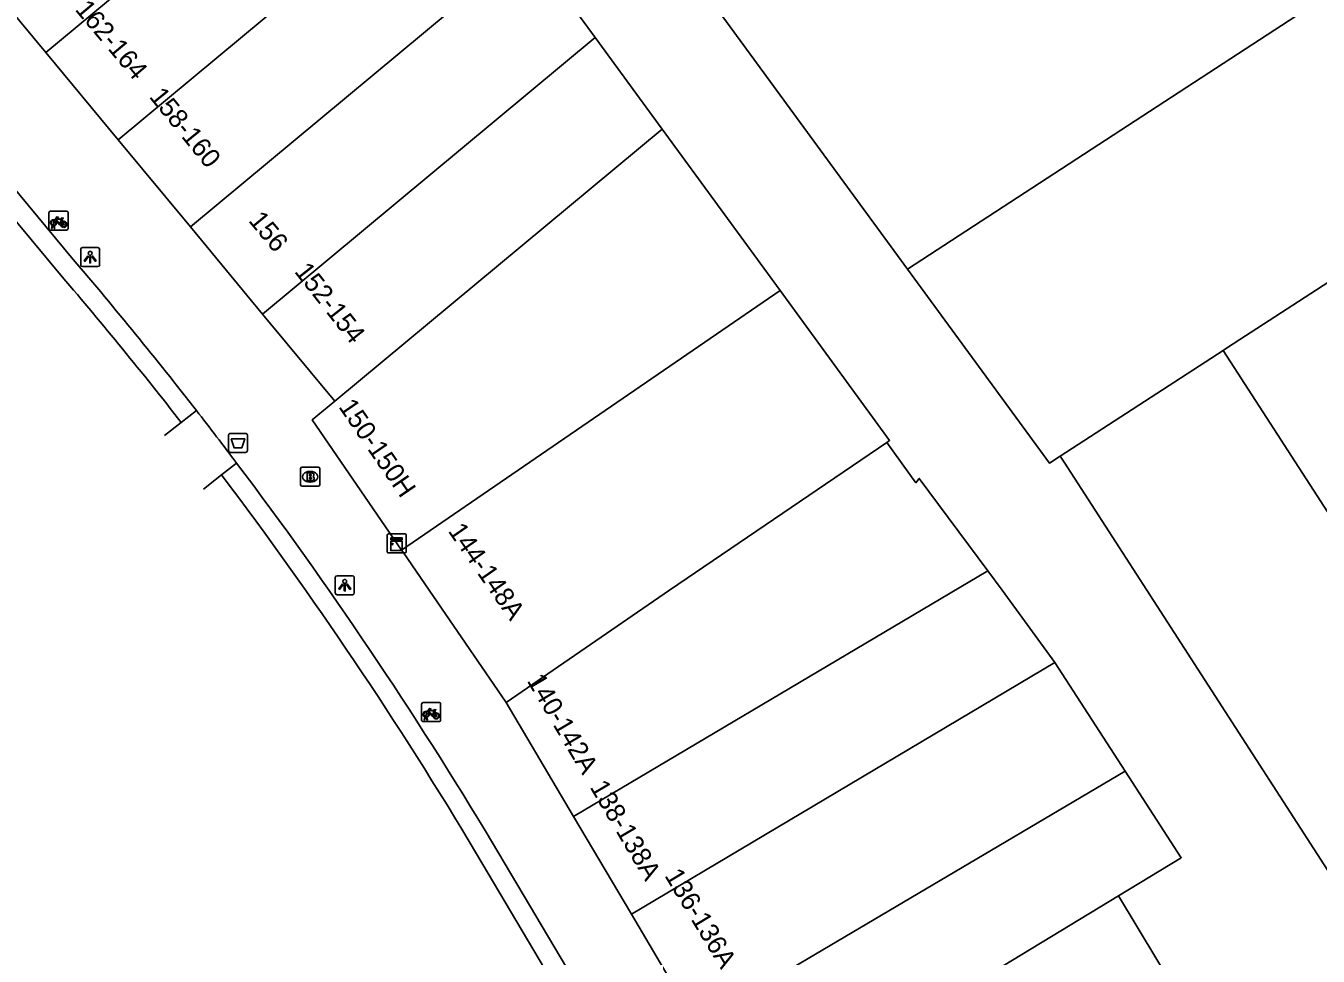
# Model space of a CAD drawing. Extents: x 160861 to 161308, y 384024 to 384878.
# Drawn here: x 161015.6 to 161083.4, y 384480.8 to 384529.6 of the extents above; entities that cross this region are included whole.
import ezdxf

# ---------------------------------------------------------------- set-up
doc = ezdxf.new("R2010")
doc.units = 0
for name, color, linetype in [('IMGEO_Afvalbak', 7, 'Continuous'), ('IMGEO_Brandkraan', 7, 'Continuous'), ('IMGEO_Fietsenrek', 7, 'Continuous'), ('IMGEO_Fietspad_gesloten', 7, 'Continuous'), ('IMGEO_Fietspad_open', 7, 'Continuous'), ('IMGEO_Kast', 7, 'Continuous'), ('IMGEO_Lichtpunt', 7, 'Continuous'), ('IMGEO_Pand', 7, 'Continuous'), ('IMGEO_Pand_nummerreeks', 7, 'Continuous')]:
    doc.layers.add(name, color=color, linetype=linetype)

msp = doc.modelspace()

# ---------------------------------------------------------------- linework, layer by layer
at = {"layer": 'IMGEO_Afvalbak'}
for p, q in [((161026.246, 384507.334), (161026.246, 384508.134)), ((161026.246, 384508.134), (161026.246, 384507.334)), ((161026.346, 384508.234), (161027.136, 384508.234)), ((161027.136, 384508.234), (161026.346, 384508.234)), ((161027.236, 384508.134), (161027.236, 384507.334)), ((161027.236, 384507.334), (161027.236, 384508.134)), ((161027.136, 384507.234), (161026.346, 384507.234)), ((161026.346, 384507.234), (161027.136, 384507.234))]:
    msp.add_line(p, q, dxfattribs=at)
msp.add_lwpolyline([(161026.389, 384507.948), (161027.093, 384507.948), (161026.944, 384507.478), (161026.538, 384507.478), (161026.389, 384507.948)], dxfattribs=at)
for centre, start, end in [((161026.346, 384508.134), 90, 180), ((161026.346, 384508.134), 90, 180), ((161027.136, 384508.134), 0, 90), ((161027.136, 384508.134), 360, 90), ((161026.346, 384507.334), 180, 270), ((161026.346, 384507.334), 180, 270), ((161027.136, 384507.334), 270, 0), ((161027.136, 384507.334), 270, 0)]:
    msp.add_arc(centre, 0.1, start, end, dxfattribs=at)
at = {"layer": 'IMGEO_Brandkraan'}
for p, q in [((161030.024, 384505.531), (161030.024, 384506.383)), ((161030.099, 384506.457), (161030.951, 384506.457)), ((161031.025, 384506.383), (161031.025, 384505.531)), ((161030.512, 384506.237), (161030.537, 384506.237)), ((161030.951, 384505.457), (161030.099, 384505.457)), ((161030.535, 384505.677), (161030.51, 384505.677))]:
    msp.add_line(p, q, dxfattribs=at)
for points in [[(161030.024, 384505.531), (161030.024, 384506.383)], [(161030.099, 384506.457), (161030.951, 384506.457)], [(161031.025, 384506.383), (161031.025, 384505.531)], [(161030.372, 384506.157), (161030.372, 384505.757), (161030.585, 384505.757)], [(161030.603, 384506.157), (161030.372, 384506.157)], [(161030.551, 384506.076), (161030.497, 384506.076), (161030.497, 384506)], [(161030.497, 384506), (161030.55, 384506)], [(161030.559, 384505.924), (161030.497, 384505.924), (161030.497, 384505.843)], [(161030.497, 384505.843), (161030.559, 384505.843)], [(161030.951, 384505.457), (161030.099, 384505.457)]]:
    msp.add_lwpolyline(points, dxfattribs=at)
for centre, radius, start, end in [((161030.101, 384506.381), 0.0765, 91.55205, 178.44795), ((161030.101, 384506.381), 0.0765, 91.55205, 178.44795), ((161030.949, 384506.381), 0.0765, 1.55205, 88.44795), ((161030.949, 384506.381), 0.0765, 1.55205, 88.44795), ((161030.552, 384506.038), 0.0379, 267.82845, 90.93552), ((161030.56, 384505.883), 0.0404, 269.87594, 90.50774), ((161030.591, 384506.008), 0.251, 268.66757, 293.53466), ((161030.607, 384506.012), 0.145, 59.4692, 91.53667), ((161030.632, 384506.059), 0.0922, 285.51372, 58.15012), ((161030.637, 384505.867), 0.105, 301.31148, 78.98903), ((161030.101, 384505.533), 0.0765, 181.55205, 268.44795), ((161030.101, 384505.533), 0.0765, 181.55205, 268.44795), ((161030.949, 384505.533), 0.0765, 271.55205, 358.44795), ((161030.949, 384505.533), 0.0765, 271.55205, 358.44795)]:
    msp.add_arc(centre, radius, start, end, dxfattribs=at)
for centre, major_axis, ratio, start_param, end_param in [((161030.511, 384505.957), (-0.387, 0.002), 0.722429, 4.712389, 7.853982), ((161030.536, 384505.957), (-0.39, 0.002), 0.717154, 1.570796, 4.712389)]:
    msp.add_ellipse(centre, major_axis=major_axis, ratio=ratio, start_param=start_param, end_param=end_param, dxfattribs=at)
at = {"layer": 'IMGEO_Fietsenrek'}
for p, q in [((161016.83, 384518.972), (161016.83, 384519.813)), ((161016.83, 384519.813), (161016.83, 384518.972)), ((161016.905, 384519.897), (161017.746, 384519.897)), ((161017.746, 384519.897), (161016.905, 384519.897)), ((161017.517, 384519.446), (161017.553, 384519.351)), ((161017.83, 384519.822), (161017.83, 384518.981)), ((161017.83, 384518.981), (161017.83, 384519.822)), ((161017.755, 384518.897), (161016.914, 384518.897)), ((161016.914, 384518.897), (161017.755, 384518.897)), ((161016.957, 384518.981), (161016.996, 384519.141)), ((161016.991, 384518.981), (161016.957, 384518.981)), ((161017.026, 384519.129), (161016.991, 384518.981)), ((161017.068, 384519.153), (161017.067, 384519.157)), ((161017.109, 384518.981), (161017.075, 384519.123)), ((161017.099, 384519.164), (161017.1, 384519.157)), ((161017.107, 384519.127), (161017.142, 384518.981)), ((161017.142, 384518.981), (161017.109, 384518.981)), ((161036.368, 384493.185), (161036.368, 384494.026)), ((161036.368, 384494.026), (161036.368, 384493.185)), ((161036.443, 384494.11), (161037.284, 384494.11)), ((161037.284, 384494.11), (161036.443, 384494.11)), ((161037.055, 384493.659), (161037.091, 384493.564)), ((161037.368, 384494.035), (161037.368, 384493.194)), ((161037.368, 384493.194), (161037.368, 384494.035)), ((161037.293, 384493.11), (161036.452, 384493.11)), ((161036.452, 384493.11), (161037.293, 384493.11)), ((161036.495, 384493.194), (161036.534, 384493.354)), ((161036.529, 384493.194), (161036.495, 384493.194)), ((161036.564, 384493.342), (161036.529, 384493.194)), ((161036.606, 384493.366), (161036.605, 384493.37)), ((161036.647, 384493.194), (161036.613, 384493.336)), ((161036.637, 384493.377), (161036.638, 384493.37)), ((161036.645, 384493.34), (161036.68, 384493.194)), ((161036.68, 384493.194), (161036.647, 384493.194))]:
    msp.add_line(p, q, dxfattribs=at)
for points in [[(161017.164, 384519.371), (161017.112, 384519.281), (161017.072, 384519.256), (161017.073, 384519.303), (161017.128, 384519.397)], [(161017.143, 384519.423), (161017.238, 384519.587), (161017.324, 384519.573), (161017.326, 384519.564), (161017.27, 384519.553), (161017.243, 384519.508), (161017.499, 384519.467)], [(161017.439, 384519.179), (161017.389, 384519.179), (161017.198, 384519.43), (161017.179, 384519.398)], [(161017.486, 384519.442), (161017.229, 384519.483), (161017.212, 384519.454), (161017.379, 384519.234), (161017.486, 384519.442)], [(161017.534, 384519.344), (161017.504, 384519.421), (161017.395, 384519.203), (161017.438, 384519.203)], [(161017.468, 384519.203), (161017.588, 384519.202), (161017.544, 384519.316)], [(161017.564, 384519.323), (161017.619, 384519.178), (161017.469, 384519.178)], [(161017.499, 384519.467), (161017.524, 384519.516), (161017.518, 384519.52), (161017.495, 384519.524), (161017.483, 384519.531), (161017.482, 384519.534), (161017.484, 384519.539), (161017.579, 384519.524), (161017.581, 384519.514), (161017.571, 384519.501), (161017.559, 384519.495), (161017.545, 384519.501), (161017.517, 384519.446)], [(161036.702, 384493.584), (161036.65, 384493.494), (161036.61, 384493.469), (161036.611, 384493.516), (161036.666, 384493.61)], [(161036.681, 384493.636), (161036.776, 384493.8), (161036.862, 384493.786), (161036.864, 384493.777), (161036.808, 384493.766), (161036.781, 384493.721), (161037.037, 384493.68)], [(161036.977, 384493.392), (161036.927, 384493.392), (161036.736, 384493.643), (161036.717, 384493.611)], [(161037.024, 384493.655), (161036.767, 384493.696), (161036.75, 384493.667), (161036.917, 384493.447), (161037.024, 384493.655)], [(161037.072, 384493.557), (161037.042, 384493.634), (161036.933, 384493.416), (161036.976, 384493.416)], [(161037.006, 384493.416), (161037.126, 384493.415), (161037.082, 384493.529)], [(161037.102, 384493.536), (161037.157, 384493.391), (161037.007, 384493.391)], [(161037.037, 384493.68), (161037.062, 384493.729), (161037.056, 384493.733), (161037.033, 384493.737), (161037.021, 384493.744), (161037.02, 384493.747), (161037.022, 384493.752), (161037.117, 384493.737), (161037.119, 384493.727), (161037.109, 384493.714), (161037.097, 384493.708), (161037.083, 384493.714), (161037.055, 384493.659)]]:
    msp.add_lwpolyline(points, dxfattribs=at)
for centre, radius, start, end in [((161016.908, 384519.819), 0.0779, 92.4484, 184.28452), ((161016.908, 384519.819), 0.0779, 92.4484, 184.28452), ((161017.07, 384519.282), 0.159, 62.67661, 242.13685), ((161017.07, 384519.282), 0.129, 63.31916, 238.90302), ((161017.07, 384519.282), 0.129, 283.60429, 43.43025), ((161017.07, 384519.282), 0.159, 283.5766, 46.60424), ((161017.597, 384519.198), 0.159, 113.3408, 178.32165), ((161017.597, 384519.198), 0.159, 187.0065, 105.77075), ((161017.597, 384519.198), 0.129, 113.92302, 177.95563), ((161017.597, 384519.198), 0.129, 188.67146, 104.58832), ((161017.752, 384519.819), 0.0779, 2.4484, 94.28452), ((161017.752, 384519.819), 0.0779, 2.4484, 94.28452), ((161016.908, 384518.975), 0.0779, 182.4484, 274.28452), ((161016.908, 384518.975), 0.0779, 182.4484, 274.28452), ((161017.05, 384519.153), 0.0499, 12.8025, 158.69338), ((161017.07, 384519.282), 0.159, 253.99666, 271.78671), ((161017.05, 384519.153), 0.0174, 12.8025, 163.45023), ((161017.07, 384519.282), 0.129, 253.41502, 269.02044), ((161017.752, 384518.975), 0.0779, 272.4484, 4.28452), ((161017.752, 384518.975), 0.0779, 272.4484, 4.28452), ((161036.446, 384494.032), 0.0779, 92.4484, 184.28452), ((161036.446, 384494.032), 0.0779, 92.4484, 184.28452), ((161036.608, 384493.495), 0.159, 62.67661, 242.13685), ((161036.608, 384493.495), 0.129, 63.31916, 238.90302), ((161036.608, 384493.495), 0.129, 283.60429, 43.43025), ((161036.608, 384493.495), 0.159, 283.5766, 46.60424), ((161037.135, 384493.411), 0.159, 113.3408, 178.32165), ((161037.135, 384493.411), 0.159, 187.0065, 105.77075), ((161037.135, 384493.411), 0.129, 113.92302, 177.95563), ((161037.135, 384493.411), 0.129, 188.67146, 104.58832), ((161037.29, 384494.032), 0.0779, 2.4484, 94.28452), ((161037.29, 384494.032), 0.0779, 2.4484, 94.28452), ((161036.446, 384493.188), 0.0779, 182.4484, 274.28452), ((161036.446, 384493.188), 0.0779, 182.4484, 274.28452), ((161036.588, 384493.366), 0.0499, 12.8025, 158.69338), ((161036.608, 384493.495), 0.159, 253.99666, 271.78671), ((161036.588, 384493.366), 0.0174, 12.8025, 163.45023), ((161036.608, 384493.495), 0.129, 253.41502, 269.02044), ((161037.29, 384493.188), 0.0779, 272.4484, 4.28452), ((161037.29, 384493.188), 0.0779, 272.4484, 4.28452)]:
    msp.add_arc(centre, radius, start, end, dxfattribs=at)
at = {"layer": 'IMGEO_Fietspad_gesloten'}
for points in [[(161017.521, 384516.451), (160978.487, 384563.462)], [(161022.895, 384508.122), (161023.763, 384508.809)], [(161024.93, 384505.299), (161025.88, 384506.051)], [(161062.919, 384446.259), (161039.255, 384486.177)]]:
    msp.add_lwpolyline(points, dxfattribs=at)
for centre, radius, start, end in [((160850.658, 384373.787), 219.536, 37.9543, 40.52973), ((160849.822, 384373.128), 220.601, 30.82769, 37.05261)]:
    msp.add_arc(centre, radius, start, end, dxfattribs=at)
at = {"layer": 'IMGEO_Fietspad_open'}
for points in [[(161018.1, 384517.358), (160990.437, 384550.764), (160979.348, 384564.156)], [(161024.556, 384509.436), (161023.763, 384508.809)], [(161025.88, 384506.051), (161026.669, 384506.676)], [(161063.799, 384446.778), (161040.086, 384486.747)]]:
    msp.add_lwpolyline(points, dxfattribs=at)
for centre, radius, start, end in [((160847.353, 384371.617), 224.489, 37.8739, 40.48243), ((160849.227, 384373.018), 222.149, 36.98868, 37.88519), ((160846.585, 384370.955), 225.5, 30.89645, 37.00358)]:
    msp.add_arc(centre, radius, start, end, dxfattribs=at)
at = {"layer": 'IMGEO_Kast'}
for p, q in [((161034.56, 384502.034), (161034.56, 384502.875)), ((161034.56, 384502.875), (161034.56, 384502.034)), ((161034.635, 384502.959), (161035.476, 384502.959)), ((161035.476, 384502.959), (161034.635, 384502.959)), ((161035.56, 384502.884), (161035.56, 384502.043)), ((161035.56, 384502.043), (161035.56, 384502.884)), ((161035.485, 384501.959), (161034.644, 384501.959)), ((161034.644, 384501.959), (161035.485, 384501.959))]:
    msp.add_line(p, q, dxfattribs=at)
for points in [[(161034.755, 384502.749), (161035.355, 384502.749), (161035.355, 384502.664), (161034.755, 384502.664), (161034.755, 384502.749)], [(161034.755, 384502.574), (161035.355, 384502.574), (161035.355, 384502.085), (161034.755, 384502.085), (161034.755, 384502.574)]]:
    msp.add_lwpolyline(points, dxfattribs=at)
msp.add_circle((161034.839, 384502.423), 0.0377, dxfattribs=at)
for centre, start, end in [((161034.638, 384502.881), 92.4484, 184.28452), ((161034.638, 384502.881), 92.4484, 184.28452), ((161035.482, 384502.881), 2.4484, 94.28452), ((161035.482, 384502.881), 2.4484, 94.28452), ((161034.638, 384502.037), 182.4484, 274.28452), ((161034.638, 384502.037), 182.4484, 274.28452), ((161035.482, 384502.037), 272.4484, 4.28452), ((161035.482, 384502.037), 272.4484, 4.28452)]:
    msp.add_arc(centre, 0.0779, start, end, dxfattribs=at)
at = {"layer": 'IMGEO_Lichtpunt'}
for p, q in [((161019.393, 384517.978), (161018.585, 384517.978)), ((161019.393, 384517.978), (161018.585, 384517.978)), ((161018.491, 384517.883), (161018.491, 384517.076)), ((161018.491, 384517.883), (161018.491, 384517.076)), ((161019.487, 384517.076), (161019.487, 384517.883)), ((161019.487, 384517.076), (161019.487, 384517.883)), ((161018.585, 384516.982), (161019.393, 384516.982)), ((161018.585, 384516.982), (161019.393, 384516.982)), ((161031.839, 384500.671), (161031.839, 384499.864)), ((161031.839, 384500.671), (161031.839, 384499.864)), ((161032.741, 384500.766), (161031.933, 384500.766)), ((161032.741, 384500.766), (161031.933, 384500.766)), ((161032.835, 384499.864), (161032.835, 384500.671)), ((161032.835, 384499.864), (161032.835, 384500.671)), ((161031.933, 384499.77), (161032.741, 384499.77)), ((161031.933, 384499.77), (161032.741, 384499.77))]:
    msp.add_line(p, q, dxfattribs=at)
for points in [[(161018.865, 384517.547), (161018.904, 384517.519), (161018.716, 384517.257), (161018.678, 384517.284), (161018.865, 384517.547)], [(161018.967, 384517.499), (161019.014, 384517.499), (161019.014, 384517.177), (161018.967, 384517.177), (161018.967, 384517.499)], [(161019.077, 384517.519), (161019.115, 384517.546), (161019.302, 384517.284), (161019.263, 384517.256), (161019.077, 384517.519)], [(161032.213, 384500.335), (161032.252, 384500.307), (161032.064, 384500.045), (161032.026, 384500.072), (161032.213, 384500.335)], [(161032.315, 384500.287), (161032.362, 384500.287), (161032.362, 384499.965), (161032.315, 384499.965), (161032.315, 384500.287)], [(161032.425, 384500.307), (161032.463, 384500.334), (161032.65, 384500.072), (161032.611, 384500.044), (161032.425, 384500.307)]]:
    msp.add_lwpolyline(points, dxfattribs=at)
for centre in [(161018.99, 384517.681), (161032.338, 384500.469)]:
    msp.add_circle(centre, 0.0994, dxfattribs=at)
for centre, start, end in [((161018.585, 384517.883), 90, 180), ((161018.585, 384517.883), 90, 180), ((161019.393, 384517.883), 0, 90), ((161019.393, 384517.883), 0, 90), ((161018.585, 384517.076), 180, 270), ((161018.585, 384517.076), 180, 270), ((161019.393, 384517.076), 270, 0), ((161019.393, 384517.076), 270, 360), ((161031.933, 384500.671), 90, 180), ((161031.933, 384500.671), 90, 180), ((161032.741, 384500.671), 0, 90), ((161032.741, 384500.671), 0, 90), ((161031.933, 384499.864), 180, 270), ((161031.933, 384499.864), 180, 270), ((161032.741, 384499.864), 270, 0), ((161032.741, 384499.864), 270, 360)]:
    msp.add_arc(centre, 0.0946, start, end, dxfattribs=at)
at = {"layer": 'IMGEO_Pand'}
for points in [[(161034.956, 384543.407), (161016.665, 384528.211)], [(161038.456, 384538.613), (161020.454, 384523.638)], [(161092.65, 384536.939), (161061.847, 384516.849)], [(161016.665, 384528.211), (161011.287, 384534.701)], [(161024.243, 384519.066), (161041.965, 384533.808)], [(161045.474, 384529.002), (161041.965, 384533.808)], [(161050.778, 384531.991), (161061.847, 384516.849)], [(161045.474, 384529.002), (161028.032, 384514.494)], [(161048.983, 384524.197), (161045.474, 384529.002)], [(161020.454, 384523.638), (161016.665, 384528.211)], [(161099.532, 384526.285), (161078.632, 384512.731), (161078.403, 384512.582)], [(161031.821, 384509.921), (161048.983, 384524.197)], [(161048.983, 384524.197), (161055.172, 384515.721)], [(161024.243, 384519.066), (161020.454, 384523.638)], [(161028.032, 384514.494), (161024.243, 384519.066)], [(161061.847, 384516.849), (161064.523, 384513.188), (161069.287, 384506.671), (161069.859, 384507.042)], [(161055.172, 384515.721), (161035.318, 384502.112)], [(161060.762, 384507.759), (161060.912, 384507.86), (161055.172, 384515.721)], [(161028.032, 384514.494), (161031.821, 384509.921)], [(161069.859, 384507.042), (161078.403, 384512.582)], [(161078.403, 384512.582), (161086.528, 384500), (161089.266, 384495.761)], [(161035.318, 384502.112), (161030.638, 384508.94), (161031.821, 384509.921)], [(161060.762, 384507.759), (161049.367, 384500), (161040.804, 384494.109)], [(161066.061, 384501.015), (161062.467, 384505.869), (161062.285, 384505.641), (161060.762, 384507.759)], [(161069.859, 384507.042), (161070.066, 384506.722), (161074.406, 384500), (161086.57, 384481.163)], [(161035.318, 384502.112), (161035.397, 384501.998), (161036.766, 384500), (161040.804, 384494.109)], [(161066.061, 384501.015), (161044.336, 384488.136)], [(161069.571, 384496.22), (161066.804, 384500), (161066.061, 384501.015)], [(161047.368, 384483.008), (161069.571, 384496.22)], [(161073.262, 384490.514), (161069.571, 384496.22)], [(161040.804, 384494.109), (161044.336, 384488.136)], [(161050.789, 384477.224), (161073.262, 384490.514)], [(161072.904, 384483.963), (161076.199, 384485.966), (161073.262, 384490.514)], [(161044.336, 384488.136), (161047.368, 384483.008)], [(161072.904, 384483.963), (161053.697, 384472.306)], [(161075.954, 384478.925), (161072.904, 384483.963)], [(161047.368, 384483.008), (161050.789, 384477.224)]]:
    msp.add_lwpolyline(points, dxfattribs=at)

# ---------------------------------------------------------------- texts
at = {"layer": 'IMGEO_Pand_nummerreeks'}
for s, rotation, p in [('162-164', 309.98689, (161018.158, 384530.457)), ('158-160', 309.02568, (161022.048, 384525.884)), ('156', 309.64991, (161027.256, 384519.379)), ('152-154', 308.21103, (161029.664, 384516.713)), ('150-150H', 304.42882, (161031.986, 384509.626)), ('144-148A', 304.73169, (161037.726, 384503.109)), ('140-142A', 300.59574, (161041.869, 384495.256)), ('138-138A', 300.59574, (161045.167, 384489.678)), ('136-136A', 301.10881, (161049.084, 384485.034))]:
    msp.add_text(s, height=1, rotation=rotation, dxfattribs=at).set_placement(p)

doc.saveas('drawing.dxf')
